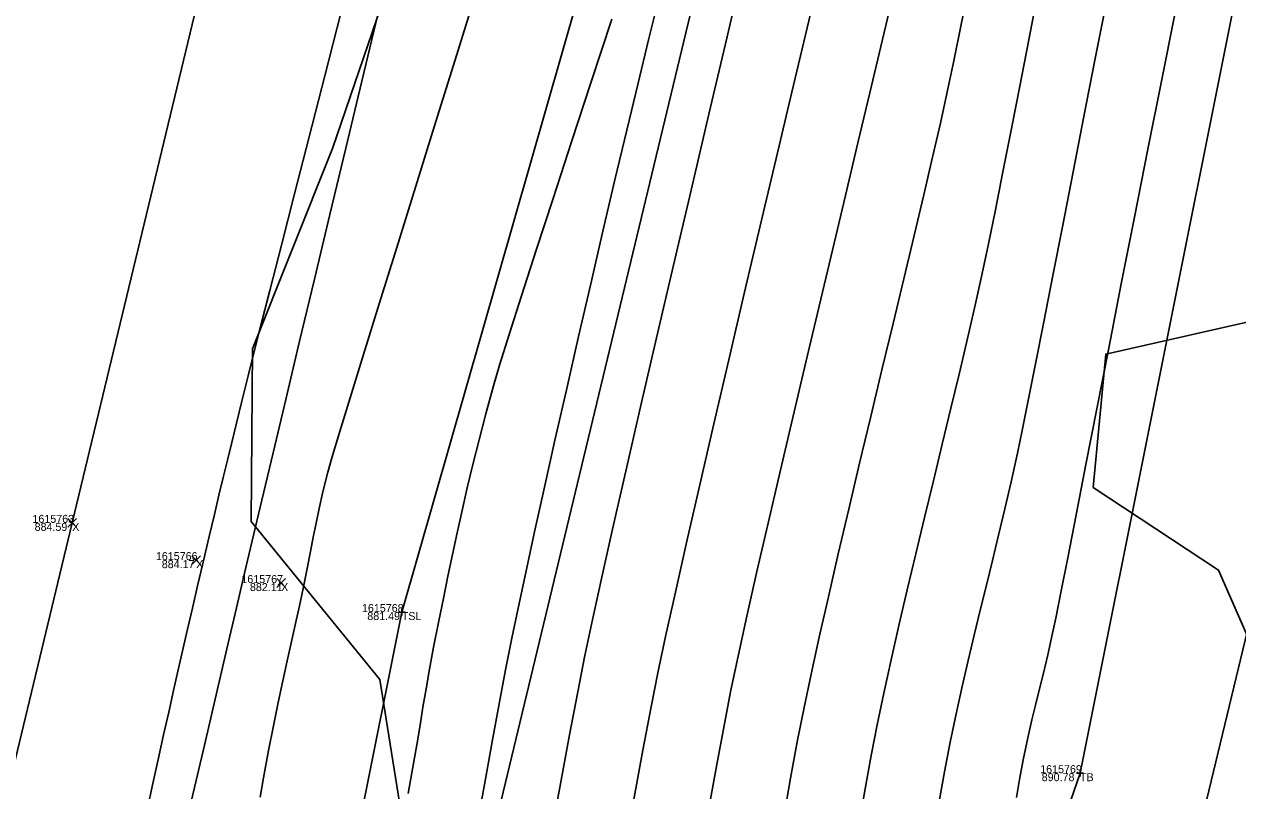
# Model space of a CAD drawing. Extents: x 1957117 to 1971063, y 701601 to 715861.
# Drawn here: x 1962920.3 to 1962973.3, y 704579.4 to 704613 of the extents above; entities that cross this region are included whole.
import ezdxf

# ---------------------------------------------------------------- set-up
doc = ezdxf.new("R2010")
doc.units = 0
for name, color, linetype in [('AP_X_Lights', 7, 'Continuous'), ('DT_X_Break_Line', 7, 'Continuous'), ('DT_X_Contour_Major', 7, 'Continuous'), ('DT_X_Contour_Minor', 7, 'Continuous'), ('DT_X_TIN_Hull', 7, 'Continuous'), ('GE_X_CL_20', 7, 'Continuous'), ('HY_X_Water_Edge', 7, 'Continuous'), ('PV_P_Drive', 7, 'Continuous'), ('PV_P_Shoulder', 7, 'Continuous'), ('RS_Raster1', 7, 'Continuous'), ('RW_X_Esmt_RR', 7, 'Continuous'), ('SC_Scratch1', 7, 'Continuous'), ('VG_X_Tree_Line_Rt', 7, 'Continuous')]:
    doc.layers.add(name, color=color, linetype=linetype)

msp = doc.modelspace()

# ---------------------------------------------------------------- linework, layer by layer
at = {"layer": 'AP_X_Lights'}
for p, q in [((1962922.169, 704590.974), (1962922.557, 704591.364)), ((1962922.169, 704591.364), (1962922.557, 704590.974)), ((1962927.589, 704589.342), (1962927.977, 704589.732)), ((1962927.589, 704589.732), (1962927.977, 704589.342)), ((1962931.308, 704588.338), (1962931.696, 704588.728)), ((1962931.308, 704588.728), (1962931.696, 704588.338))]:
    msp.add_line(p, q, dxfattribs=at)
at = {"layer": 'DT_X_Break_Line'}
for points in [[(1962854.549, 704243.654), (1962868.069, 704295.231), (1962879.669, 704344.313), (1962892.757, 704392.318), (1962905.964, 704443.142), (1962917.718, 704492.375), (1962926.962, 704538.336), (1962936.778, 704587.265), (1962949.215, 704630.669), (1962963.968, 704683.754), (1962972.038, 704733.348), (1962988.206, 704780.999), (1962994.689, 704830.943), (1963004.932, 704879.138), (1963021.822, 704927.498), (1963031.944, 704976.286), (1963045.21, 705027.355), (1963059.618, 705072.384), (1963067.267, 705121.949)], [(1963081.686, 705067.168), (1963070.617, 705018.992), (1963060.629, 704969.66), (1963044.793, 704921.859), (1963033.624, 704869.219), (1963022.038, 704824.561), (1963012.554, 704778.141), (1962998.858, 704727.004), (1962987.967, 704677.611), (1962975.675, 704626.305), (1962966.447, 704580.213), (1962950.262, 704533.092), (1962939.515, 704481.257), (1962926.044, 704436.037), (1962917.68, 704386.811), (1962906.11, 704337.415), (1962892.064, 704289.931), (1962881.011, 704234.451)]]:
    msp.add_lwpolyline(points, dxfattribs=at)
at = {"layer": 'DT_X_Contour_Major'}
for points in [[(1962955.141, 704615.497), (1962954.508, 704612.834), (1962953.841, 704610.026), (1962953.153, 704607.121), (1962952.455, 704604.168), (1962951.76, 704601.214), (1962951.079, 704598.309), (1962950.425, 704595.5), (1962949.811, 704592.837), (1962949.247, 704590.367), (1962948.747, 704588.139), (1962948.322, 704586.201), (1962947.984, 704584.601), (1962947.689, 704583.112), (1962947.33, 704581.224), (1962946.915, 704578.988)], [(1962955.141, 704615.497), (1962954.508, 704612.834), (1962953.841, 704610.026), (1962953.153, 704607.121), (1962952.455, 704604.168), (1962951.76, 704601.214), (1962951.079, 704598.309), (1962950.425, 704595.5), (1962949.811, 704592.837), (1962949.247, 704590.367), (1962948.747, 704588.139), (1962948.322, 704586.201), (1962947.984, 704584.601), (1962947.689, 704583.112), (1962947.33, 704581.224), (1962946.915, 704578.988)], [(1962970.592, 704613.428), (1962970.007, 704610.499), (1962969.416, 704607.523), (1962968.829, 704604.551), (1962968.255, 704601.634), (1962967.704, 704598.822), (1962967.185, 704596.166), (1962966.706, 704593.717), (1962966.277, 704591.525), (1962965.908, 704589.641), (1962965.607, 704588.115), (1962965.384, 704586.997), (1962965.249, 704586.34), (1962965.035, 704585.386), (1962964.848, 704584.596), (1962964.677, 704583.904), (1962964.512, 704583.244), (1962964.344, 704582.551), (1962964.164, 704581.759), (1962963.961, 704580.804), (1962963.795, 704579.934), (1962963.666, 704579.153)], [(1962970.592, 704613.428), (1962970.007, 704610.499), (1962969.416, 704607.523), (1962968.829, 704604.551), (1962968.255, 704601.634), (1962967.704, 704598.822), (1962967.185, 704596.166), (1962966.706, 704593.717), (1962966.277, 704591.525), (1962965.908, 704589.641), (1962965.607, 704588.115), (1962965.384, 704586.997), (1962965.249, 704586.34), (1962965.035, 704585.386), (1962964.848, 704584.596), (1962964.677, 704583.904), (1962964.512, 704583.244), (1962964.344, 704582.551), (1962964.164, 704581.759), (1962963.961, 704580.804), (1962963.795, 704579.934), (1962963.666, 704579.153)]]:
    msp.add_lwpolyline(points, dxfattribs=at)
at = {"layer": 'DT_X_Contour_Minor'}
for points in [[(1962951.761, 704615.652), (1962950.992, 704612.385), (1962950.211, 704609.06), (1962949.431, 704605.73), (1962948.665, 704602.449), (1962947.927, 704599.271), (1962947.228, 704596.249), (1962946.582, 704593.437), (1962946.002, 704590.889), (1962945.501, 704588.658), (1962945.093, 704586.797), (1962944.789, 704585.361), (1962944.474, 704583.776), (1962944.114, 704581.89), (1962943.717, 704579.747), (1962943.29, 704577.393)], [(1962951.761, 704615.652), (1962950.992, 704612.385), (1962950.211, 704609.06), (1962949.431, 704605.73), (1962948.665, 704602.449), (1962947.927, 704599.271), (1962947.228, 704596.249), (1962946.582, 704593.437), (1962946.002, 704590.889), (1962945.501, 704588.658), (1962945.093, 704586.797), (1962944.789, 704585.361), (1962944.474, 704583.776), (1962944.114, 704581.89), (1962943.717, 704579.747), (1962943.29, 704577.393)], [(1962930.588, 704579.166), (1962930.732, 704580.016), (1962930.952, 704581.199), (1962931.166, 704582.292), (1962931.373, 704583.305), (1962931.573, 704584.248), (1962931.766, 704585.133), (1962931.952, 704585.971), (1962932.13, 704586.771), (1962932.301, 704587.544), (1962932.464, 704588.302), (1962932.643, 704589.178), (1962932.785, 704589.909), (1962932.907, 704590.55), (1962933.027, 704591.162), (1962933.161, 704591.801), (1962933.328, 704592.525), (1962933.544, 704593.392), (1962933.723, 704594.02), (1962934.054, 704595.123), (1962934.521, 704596.648), (1962935.105, 704598.542), (1962935.79, 704600.751), (1962936.557, 704603.222), (1962937.39, 704605.9), (1962938.271, 704608.734), (1962939.182, 704611.668), (1962940.105, 704614.651)], [(1962930.588, 704579.166), (1962930.732, 704580.016), (1962930.952, 704581.199), (1962931.166, 704582.292), (1962931.373, 704583.305), (1962931.573, 704584.248), (1962931.766, 704585.133), (1962931.952, 704585.971), (1962932.13, 704586.771), (1962932.301, 704587.544), (1962932.464, 704588.302), (1962932.643, 704589.178), (1962932.785, 704589.909), (1962932.907, 704590.55), (1962933.027, 704591.162), (1962933.161, 704591.801), (1962933.328, 704592.525), (1962933.544, 704593.392), (1962933.723, 704594.02), (1962934.054, 704595.123), (1962934.521, 704596.648), (1962935.105, 704598.542), (1962935.79, 704600.751), (1962936.557, 704603.222), (1962937.39, 704605.9), (1962938.271, 704608.734), (1962939.182, 704611.668), (1962940.105, 704614.651)], [(1962961.554, 704614.491), (1962961.24, 704612.909), (1962960.931, 704611.395), (1962960.627, 704609.965), (1962960.339, 704608.663), (1962959.998, 704607.175), (1962959.613, 704605.526), (1962959.191, 704603.744), (1962958.741, 704601.856), (1962958.27, 704599.889), (1962957.785, 704597.869), (1962957.296, 704595.825), (1962956.808, 704593.782), (1962956.332, 704591.769), (1962955.873, 704589.811), (1962955.44, 704587.937), (1962955.041, 704586.173), (1962954.683, 704584.545), (1962954.375, 704583.082), (1962954.096, 704581.663), (1962953.789, 704580), (1962953.459, 704578.132)], [(1962961.554, 704614.491), (1962961.24, 704612.909), (1962960.931, 704611.395), (1962960.627, 704609.965), (1962960.339, 704608.663), (1962959.998, 704607.175), (1962959.613, 704605.526), (1962959.191, 704603.744), (1962958.741, 704601.856), (1962958.27, 704599.889), (1962957.785, 704597.869), (1962957.296, 704595.825), (1962956.808, 704593.782), (1962956.332, 704591.769), (1962955.873, 704589.811), (1962955.44, 704587.937), (1962955.041, 704586.173), (1962954.683, 704584.545), (1962954.375, 704583.082), (1962954.096, 704581.663), (1962953.789, 704580), (1962953.459, 704578.132)], [(1962948.001, 704614.009), (1962947.577, 704612.308), (1962947.114, 704610.413), (1962946.621, 704608.36), (1962946.105, 704606.187), (1962945.577, 704603.933), (1962945.043, 704601.633), (1962944.512, 704599.326), (1962943.993, 704597.049), (1962943.495, 704594.84), (1962943.024, 704592.736), (1962942.59, 704590.775), (1962942.202, 704588.993), (1962941.867, 704587.429), (1962941.593, 704586.12), (1962941.316, 704584.73), (1962941.032, 704583.243), (1962940.743, 704581.674), (1962940.451, 704580.039), (1962940.155, 704578.356)], [(1962948.001, 704614.009), (1962947.577, 704612.308), (1962947.114, 704610.413), (1962946.621, 704608.36), (1962946.105, 704606.187), (1962945.577, 704603.933), (1962945.043, 704601.633), (1962944.512, 704599.326), (1962943.993, 704597.049), (1962943.495, 704594.84), (1962943.024, 704592.736), (1962942.59, 704590.775), (1962942.202, 704588.993), (1962941.867, 704587.429), (1962941.593, 704586.12), (1962941.316, 704584.73), (1962941.032, 704583.243), (1962940.743, 704581.674), (1962940.451, 704580.039), (1962940.155, 704578.356)], [(1962964.604, 704614.389), (1962964.202, 704612.31), (1962963.81, 704610.289), (1962963.434, 704608.356), (1962963.078, 704606.539), (1962962.745, 704604.87), (1962962.44, 704603.377), (1962962.168, 704602.09), (1962961.86, 704600.699), (1962961.527, 704599.244), (1962961.173, 704597.736), (1962960.804, 704596.187), (1962960.423, 704594.609), (1962960.037, 704593.012), (1962959.65, 704591.41), (1962959.266, 704589.813), (1962958.891, 704588.234), (1962958.529, 704586.683), (1962958.185, 704585.174), (1962957.864, 704583.716), (1962957.57, 704582.323), (1962957.31, 704580.991), (1962957.046, 704579.528), (1962956.777, 704577.957)], [(1962964.604, 704614.389), (1962964.202, 704612.31), (1962963.81, 704610.289), (1962963.434, 704608.356), (1962963.078, 704606.539), (1962962.745, 704604.87), (1962962.44, 704603.377), (1962962.168, 704602.09), (1962961.86, 704600.699), (1962961.527, 704599.244), (1962961.173, 704597.736), (1962960.804, 704596.187), (1962960.423, 704594.609), (1962960.037, 704593.012), (1962959.65, 704591.41), (1962959.266, 704589.813), (1962958.891, 704588.234), (1962958.529, 704586.683), (1962958.185, 704585.174), (1962957.864, 704583.716), (1962957.57, 704582.323), (1962957.31, 704580.991), (1962957.046, 704579.528), (1962956.777, 704577.957)], [(1962967.588, 704613.896), (1962967.1, 704611.417), (1962966.618, 704608.95), (1962966.146, 704606.533), (1962965.693, 704604.204), (1962965.263, 704602.001), (1962964.865, 704599.963), (1962964.503, 704598.127), (1962964.186, 704596.531), (1962963.919, 704595.215), (1962963.708, 704594.215), (1962963.432, 704592.968), (1962963.158, 704591.779), (1962962.887, 704590.637), (1962962.617, 704589.526), (1962962.35, 704588.435), (1962962.084, 704587.351), (1962961.819, 704586.259), (1962961.555, 704585.148), (1962961.291, 704584.003), (1962961.028, 704582.813), (1962960.766, 704581.563), (1962960.515, 704580.273), (1962960.286, 704578.971)], [(1962967.588, 704613.896), (1962967.1, 704611.417), (1962966.618, 704608.95), (1962966.146, 704606.533), (1962965.693, 704604.204), (1962965.263, 704602.001), (1962964.865, 704599.963), (1962964.503, 704598.127), (1962964.186, 704596.531), (1962963.919, 704595.215), (1962963.708, 704594.215), (1962963.432, 704592.968), (1962963.158, 704591.779), (1962962.887, 704590.637), (1962962.617, 704589.526), (1962962.35, 704588.435), (1962962.084, 704587.351), (1962961.819, 704586.259), (1962961.555, 704585.148), (1962961.291, 704584.003), (1962961.028, 704582.813), (1962960.766, 704581.563), (1962960.515, 704580.273), (1962960.286, 704578.971)], [(1962925.664, 704578.725), (1962925.861, 704579.626), (1962926.121, 704580.808), (1962926.36, 704581.888), (1962926.583, 704582.887), (1962926.795, 704583.827), (1962927, 704584.731), (1962927.203, 704585.619), (1962927.409, 704586.513), (1962927.623, 704587.436), (1962927.849, 704588.409), (1962928.094, 704589.453), (1962928.355, 704590.569), (1962928.58, 704591.528), (1962928.781, 704592.375), (1962928.966, 704593.155), (1962929.149, 704593.913), (1962929.338, 704594.692), (1962929.546, 704595.537), (1962929.782, 704596.494), (1962930.058, 704597.606), (1962930.267, 704598.439), (1962930.588, 704599.702), (1962931.007, 704601.345), (1962931.511, 704603.318), (1962932.088, 704605.574), (1962932.725, 704608.061), (1962933.41, 704610.732), (1962934.129, 704613.537)], [(1962925.664, 704578.725), (1962925.861, 704579.626), (1962926.121, 704580.808), (1962926.36, 704581.888), (1962926.583, 704582.887), (1962926.795, 704583.827), (1962927, 704584.731), (1962927.203, 704585.619), (1962927.409, 704586.513), (1962927.623, 704587.436), (1962927.849, 704588.409), (1962928.094, 704589.453), (1962928.355, 704590.569), (1962928.58, 704591.528), (1962928.781, 704592.375), (1962928.966, 704593.155), (1962929.149, 704593.913), (1962929.338, 704594.692), (1962929.546, 704595.537), (1962929.782, 704596.494), (1962930.058, 704597.606), (1962930.267, 704598.439), (1962930.588, 704599.702), (1962931.007, 704601.345), (1962931.511, 704603.318), (1962932.088, 704605.574), (1962932.725, 704608.061), (1962933.41, 704610.732), (1962934.129, 704613.537)], [(1962927.6, 704579.091), (1962928.145, 704581.44), (1962928.657, 704583.642), (1962929.127, 704585.656), (1962929.544, 704587.444), (1962929.9, 704588.966), (1962930.234, 704590.387), (1962930.653, 704592.158), (1962931.146, 704594.235), (1962931.702, 704596.569), (1962932.309, 704599.116), (1962932.958, 704601.829), (1962933.636, 704604.662), (1962934.332, 704607.568), (1962935.037, 704610.503), (1962935.738, 704613.418)], [(1962927.6, 704579.091), (1962928.145, 704581.44), (1962928.657, 704583.642), (1962929.127, 704585.656), (1962929.544, 704587.444), (1962929.9, 704588.966), (1962930.234, 704590.387), (1962930.653, 704592.158), (1962931.146, 704594.235), (1962931.702, 704596.569), (1962932.309, 704599.116), (1962932.958, 704601.829), (1962933.636, 704604.662), (1962934.332, 704607.568), (1962935.037, 704610.503), (1962935.738, 704613.418)], [(1962958.173, 704613.86), (1962957.739, 704612.023), (1962957.257, 704609.992), (1962956.735, 704607.803), (1962956.185, 704605.494), (1962955.614, 704603.101), (1962955.034, 704600.661), (1962954.453, 704598.21), (1962953.881, 704595.785), (1962953.328, 704593.423), (1962952.803, 704591.161), (1962952.316, 704589.035), (1962951.877, 704587.082), (1962951.495, 704585.339), (1962951.18, 704583.842), (1962950.891, 704582.379), (1962950.556, 704580.593), (1962950.182, 704578.526)], [(1962958.173, 704613.86), (1962957.739, 704612.023), (1962957.257, 704609.992), (1962956.735, 704607.803), (1962956.185, 704605.494), (1962955.614, 704603.101), (1962955.034, 704600.661), (1962954.453, 704598.21), (1962953.881, 704595.785), (1962953.328, 704593.423), (1962952.803, 704591.161), (1962952.316, 704589.035), (1962951.877, 704587.082), (1962951.495, 704585.339), (1962951.18, 704583.842), (1962950.891, 704582.379), (1962950.556, 704580.593), (1962950.182, 704578.526)], [(1962945.97, 704613.216), (1962945.069, 704610.476), (1962944.205, 704607.844), (1962943.396, 704605.37), (1962942.659, 704603.106), (1962942.012, 704601.102), (1962941.473, 704599.409), (1962941.059, 704598.078), (1962940.789, 704597.16), (1962940.46, 704595.948), (1962940.162, 704594.809), (1962939.892, 704593.73), (1962939.645, 704592.7), (1962939.416, 704591.706), (1962939.202, 704590.738), (1962938.997, 704589.783), (1962938.798, 704588.829), (1962938.6, 704587.865), (1962938.398, 704586.88), (1962938.17, 704585.735), (1962937.989, 704584.764), (1962937.839, 704583.908), (1962937.707, 704583.109), (1962937.578, 704582.31), (1962937.436, 704581.452), (1962937.268, 704580.478), (1962937.059, 704579.329)], [(1962945.97, 704613.216), (1962945.069, 704610.476), (1962944.205, 704607.844), (1962943.396, 704605.37), (1962942.659, 704603.106), (1962942.012, 704601.102), (1962941.473, 704599.409), (1962941.059, 704598.078), (1962940.789, 704597.16), (1962940.46, 704595.948), (1962940.162, 704594.809), (1962939.892, 704593.73), (1962939.645, 704592.7), (1962939.416, 704591.706), (1962939.202, 704590.738), (1962938.997, 704589.783), (1962938.798, 704588.829), (1962938.6, 704587.865), (1962938.398, 704586.88), (1962938.17, 704585.735), (1962937.989, 704584.764), (1962937.839, 704583.908), (1962937.707, 704583.109), (1962937.578, 704582.31), (1962937.436, 704581.452), (1962937.268, 704580.478), (1962937.059, 704579.329)]]:
    msp.add_lwpolyline(points, dxfattribs=at)
at = {"layer": 'DT_X_TIN_Hull'}
msp.add_lwpolyline([(1963062.2, 705175.46), (1963037.999, 705077.244), (1963026.56, 705028.621), (1963015.244, 704980.352), (1962992.578, 704882.771), (1962981.085, 704833.91), (1962969.384, 704785.804), (1962957.851, 704737.276), (1962945.67, 704688.173), (1962933.954, 704639.432), (1962922.363, 704591.169), (1962899.093, 704494.258), (1962887.945, 704444.945), (1962875.826, 704396.455), (1962864.548, 704347.909), (1962854.544, 704302.816), (1962839.463, 704247.251)], dxfattribs=at)
at = {"layer": 'GE_X_CL_20'}
msp.add_lwpolyline([(1963418.3, 706437.397), (1962895.621, 704261.062)], dxfattribs=at)
at = {"layer": 'HY_X_Water_Edge'}
msp.add_spline([(1963191.723, 701994.048), (1963062.047, 702441.167), (1962863.491, 703169.356), (1962827.53, 703438.691), (1962823.213, 703537.412), (1962817.962, 703593.874), (1962817.97, 703697.316), (1962828.582, 703804.235), (1962836.461, 703844.734), (1962850.687, 703896.004), (1962867.251, 703938.846), (1962873.848, 703992.355), (1962884.135, 704091.371), (1962891.241, 704140.854), (1962897.382, 704180.529), (1962905.467, 704230.979), (1962943.949, 704328.022), (1962948.537, 704378.842), (1962964.114, 704426.264), (1963004.885, 704570.73), (1963042.054, 704716.522), (1963062.038, 704814.417), (1963072.171, 704860.237), (1963090.023, 704956.798), (1963107.066, 705031.783), (1963133.773, 705105.742), (1963148.685, 705206.74), (1963175.48, 705301.059), (1963191.635, 705353.417), (1963210.988, 705447.286), (1963219.532, 705497.27), (1963230.124, 705549.475), (1963251.052, 705591.159), (1963275.289, 705693.429), (1963292.982, 705784.032), (1963302.841, 705839.645), (1963335.126, 705936.766), (1963359.752, 706046.75), (1963389.133, 706177.299), (1963417.827, 706273.456), (1963475.868, 706451.902), (1963533.782, 706640.53), (1963553.86, 706696.984), (1963580.184, 706715.425), (1963609.172, 706718.73), (1963617.062, 706714.691), (1963619.447, 706694.678), (1963564.282, 706533.07), (1963531.853, 706395.229), (1963434.4, 706006.96), (1963354.09, 705679.186), (1963237.513, 705206.07), (1963167.369, 704892.962), (1963059.145, 704434.176), (1962907.914, 703908.742), (1962877.458, 703703.326), (1962898.357, 703412.121), (1962942.65, 703052.267), (1963048.963, 702674.866), (1963191.468, 702189.666), (1963245.396, 702019.832)], degree=3, dxfattribs=at)
at = {"layer": 'PV_P_Drive'}
for p, q in [((1962936.778, 704587.411), (1962936.778, 704587.119)), ((1962936.632, 704587.265), (1962936.924, 704587.265)), ((1962936.778, 704587.265), (1962936.778, 704587.265)), ((1962966.301, 704580.213), (1962966.593, 704580.213)), ((1962966.447, 704580.359), (1962966.447, 704580.067)), ((1962966.447, 704580.213), (1962966.447, 704580.213))]:
    msp.add_line(p, q, dxfattribs=at)
at = {"layer": 'RW_X_Esmt_RR'}
msp.add_lwpolyline([(1962866.45, 704268.068), (1963123.345, 705337.727), (1963135.496, 705336.937), (1963400.797, 706441.601)], dxfattribs=at)
at = {"layer": 'VG_X_Tree_Line_Rt'}
for points in [[(1962936.253, 704614.904), (1962933.748, 704607.549), (1962930.244, 704598.782), (1962930.197, 704591.232), (1962935.819, 704584.32), (1962935.819, 704584.32), (1962936.899, 704577.551), (1962938.679, 704572.474), (1962941.333, 704567.554), (1962946.533, 704563.739), (1962955.046, 704561.526), (1962960.717, 704562.821), (1962970.12, 704566.728), (1962976.262, 704572.863)], [(1962976.498, 704579.979), (1962972.511, 704589.104), (1962967.019, 704592.72), (1962967.573, 704598.555), (1962975.098, 704600.262)]]:
    msp.add_lwpolyline(points, dxfattribs=at)

# ---------------------------------------------------------------- texts
at = {"layer": 'PV_P_Shoulder'}
for s, p in [('884.59', (1962920.718, 704590.819)), ('884.17', (1962926.279, 704589.187)), ('882.11', (1962930.137, 704588.183)), ('881.49', (1962935.271, 704586.915)), ('890.78', (1962964.772, 704579.863))]:
    msp.add_text(s, height=0.35, dxfattribs=at).set_placement(p)
at = {"layer": 'RS_Raster1'}
for s, p in [('1615763', (1962920.624, 704591.169)), ('1615766', (1962926.022, 704589.537)), ('1615767', (1962929.763, 704588.533)), ('1615768', (1962935.037, 704587.265)), ('1615769', (1962964.706, 704580.213))]:
    msp.add_text(s, height=0.35, dxfattribs=at).set_placement(p)
at = {"layer": 'SC_Scratch1'}
for s, p in [('X', (1962922.363, 704590.819)), ('X', (1962927.783, 704589.187)), ('X', (1962931.502, 704588.183)), ('TSL', (1962936.778, 704586.915)), ('TB', (1962966.447, 704579.863))]:
    msp.add_text(s, height=0.35, dxfattribs=at).set_placement(p)

doc.saveas('drawing.dxf')
